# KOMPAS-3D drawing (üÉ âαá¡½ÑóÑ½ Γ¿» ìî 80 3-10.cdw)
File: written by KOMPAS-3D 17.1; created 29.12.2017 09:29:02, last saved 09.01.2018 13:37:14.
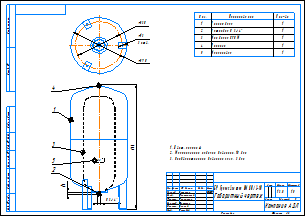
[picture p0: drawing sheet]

Sheet 1: A3, landscape, title-block layout from C:\Лощинин\GRAPHIC.LYT style 1

Title block, sheet 1: name: БР Гранлевел тип НМ 80/3-10 / Габаритный чертеж; mass: 13,8; sheets: 1; sheet format: A3; stored path: \\Fsk1\files\АП\20_PKO\02_Насосное направление\Разработка\04_Проекты разные\Баки\КД действующая\Баки Flexcon R\Компас\Чертежи\БР Гранлевел тип НМ 80_1,5-6.cdw; drawn by: Лощинин; checked by: Хантимеров; drawn by, date: 29.12.2017

Views: Вид 1, Спереди, Проекционный вид 2
Referenced files in \\Fsk1\files\АП\20_PKO\02_Насосное направление\Разработка\04_Проекты разные\Баки\КД действующая\Баки Flexcon R\Компас\: 80 литров.a3d
Referenced files in C:\Лощинин\: GRAPHIC.LYT
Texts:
  IvAn
  ADL
  АДЛ
  БР Гранлевел тип НМ 80/1,5-6
  Цвет: красный
  Максимальное рабочее давление: 10 бар
  Предварительное давление газа: 3 бар
  ACAD_ISO03W100_RGB_223_127_255_SC_0.063_THICK_0.05
  ACAD_ISO03W100_RGB_223_127_255_SC_1_THICK_0.05
  Лит-Масса-Масштаб
  Материал-Предприятие
  Масштаб
  Изм.
  Лист
  № докум.
  Подп.
  Дата
  Лит.
  Разраб.
  Пров.
  Т.контр.
  Курлыкина
  Листов
  Нач.отд.
  Щетинин
  Н.контр.
  Долгов
  Утв.
  Рашидов
  Компания АДЛ
  Изменение
  Номер документа
  Подпись
  Обозначение документа
  Наименование изделия
  Масса изделия по ГОСТ 2.109-73
  Порядковый номер листа
  Общее количество листов в документе
  Характер работы, выполненной лицом, подписавшим документ
  Наименование или индекс предприятия, выпускающего документ
  Инв. № подл.
  Подп. и дата
  Взам. инв. №
  Инв. № дубл.
  Инвентарный номер подлинника по ГОСТ 2.501-68
  Подпись принявшего подлинник в отдел технической документации
  Инвентарный номер подлинника, взамен которого выпущен данный подлинник
  Инвентарный номер дубликата по ГОСТ 2.502-68
  Подпись принявшего дубликат в отдел технической документации
  Справ. №
  Перв. примен.
  Обозначение документа, взамен или на основании которого выпущен данный документ
  Обозначение документа, в котором впервые записан данный документ
  Подпись лица, копировавшего чертеж
  Обозначение формата листа
Dimensions and other numbers on the sheet: 864; 16; 2; 5; 3; 4; 1; 330; 390; 13; 3 отв.; 1:5; 13,8; 29.12.2017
